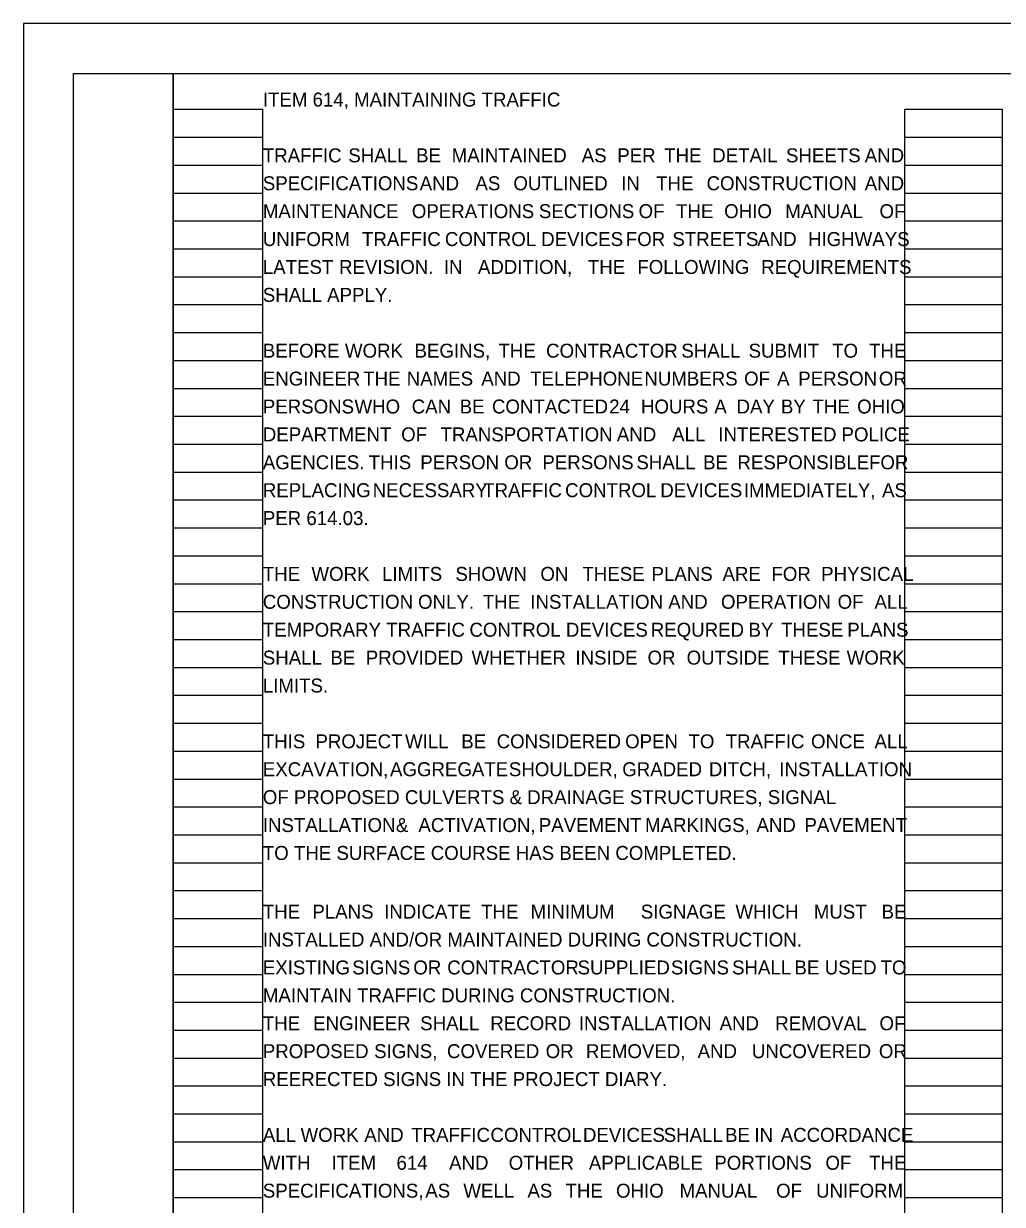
# Model space of a CAD drawing. Extents: x 0 to 34, y 0 to 22.
# Drawn here: x 0 to 9.82, y 10.15 to 22 of the extents above; entities that cross this region are included whole.
import ezdxf

# ---------------------------------------------------------------- set-up
doc = ezdxf.new("R2010")
doc.units = 0
for name, color, linetype in [('SH_Border', 7, 'Continuous'), ('SH_Cut_Line', 7, 'Continuous'), ('SH_Data', 7, 'Continuous'), ('SH_Text', 7, 'Continuous')]:
    doc.layers.add(name, color=color, linetype=linetype)

msp = doc.modelspace()

# ---------------------------------------------------------------- linework, layer by layer
at = {"layer": 'SH_Border'}
for points in [[(0.5, 21.5), (1.5, 21.5), (1.5, 0.5), (0.5, 0.5)], [(1.5, 21.5), (33.5, 21.5), (33.5, 0.5), (1.5, 0.5)]]:
    msp.add_lwpolyline(points, close=True, dxfattribs=at)
at = {"layer": 'SH_Cut_Line'}
msp.add_lwpolyline([(0, 0), (34, 0), (34, 22), (0, 22)], close=True, dxfattribs=at)
at = {"layer": 'SH_Data'}
for p, q in [((1.5, 0.98), (1.5, 21.14)), ((1.5, 21.14), (2.4, 21.14)), ((2.4, 0.98), (2.4, 21.14)), ((8.84, 0.98), (8.84, 21.14)), ((8.84, 21.14), (9.82, 21.14)), ((9.82, 0.98), (9.82, 21.14)), ((1.5, 20.86), (2.4, 20.86)), ((8.84, 20.86), (9.82, 20.86)), ((1.5, 20.58), (2.4, 20.58)), ((8.84, 20.58), (9.82, 20.58)), ((1.5, 20.3), (2.4, 20.3)), ((8.84, 20.3), (9.82, 20.3)), ((1.5, 20.02), (2.4, 20.02)), ((8.84, 20.02), (9.82, 20.02)), ((1.5, 19.74), (2.4, 19.74)), ((8.84, 19.74), (9.82, 19.74)), ((1.5, 19.46), (2.4, 19.46)), ((8.84, 19.46), (9.82, 19.46)), ((1.5, 19.18), (2.4, 19.18)), ((8.84, 19.18), (9.82, 19.18)), ((1.5, 18.9), (2.4, 18.9)), ((8.84, 18.9), (9.82, 18.9)), ((1.5, 18.62), (2.4, 18.62)), ((8.84, 18.62), (9.82, 18.62)), ((1.5, 18.34), (2.4, 18.34)), ((8.84, 18.34), (9.82, 18.34)), ((1.5, 18.06), (2.4, 18.06)), ((8.84, 18.06), (9.82, 18.06)), ((1.5, 17.78), (2.4, 17.78)), ((8.84, 17.78), (9.82, 17.78)), ((1.5, 17.5), (2.4, 17.5)), ((8.84, 17.5), (9.82, 17.5)), ((1.5, 17.22), (2.4, 17.22)), ((8.84, 17.22), (9.82, 17.22)), ((1.5, 16.94), (2.4, 16.94)), ((8.84, 16.94), (9.82, 16.94)), ((1.5, 16.66), (2.4, 16.66)), ((8.84, 16.66), (9.82, 16.66)), ((1.5, 16.38), (2.4, 16.38)), ((8.84, 16.38), (9.82, 16.38)), ((1.5, 16.1), (2.4, 16.1)), ((8.84, 16.1), (9.82, 16.1)), ((1.5, 15.82), (2.4, 15.82)), ((8.84, 15.82), (9.82, 15.82)), ((1.5, 15.54), (2.4, 15.54)), ((8.84, 15.54), (9.82, 15.54)), ((1.5, 15.26), (2.4, 15.26)), ((8.84, 15.26), (9.82, 15.26)), ((1.5, 14.98), (2.4, 14.98)), ((8.84, 14.98), (9.82, 14.98)), ((1.5, 14.7), (2.4, 14.7)), ((8.84, 14.7), (9.82, 14.7)), ((1.5, 14.42), (2.4, 14.42)), ((8.84, 14.42), (9.82, 14.42)), ((1.5, 14.14), (2.4, 14.14)), ((8.84, 14.14), (9.82, 14.14)), ((1.5, 13.86), (2.4, 13.86)), ((8.84, 13.86), (9.82, 13.86)), ((1.5, 13.58), (2.4, 13.58)), ((8.84, 13.58), (9.82, 13.58)), ((1.5, 13.3), (2.4, 13.3)), ((8.84, 13.3), (9.82, 13.3)), ((1.5, 13.02), (2.4, 13.02)), ((8.84, 13.02), (9.82, 13.02)), ((1.5, 12.74), (2.4, 12.74)), ((8.84, 12.74), (9.82, 12.74)), ((1.5, 12.46), (2.4, 12.46)), ((8.84, 12.46), (9.82, 12.46)), ((1.5, 12.18), (2.4, 12.18)), ((8.84, 12.18), (9.82, 12.18)), ((1.5, 11.9), (2.4, 11.9)), ((8.84, 11.9), (9.82, 11.9)), ((1.5, 11.62), (2.4, 11.62)), ((8.84, 11.62), (9.82, 11.62)), ((1.5, 11.34), (2.4, 11.34)), ((8.84, 11.34), (9.82, 11.34)), ((1.5, 11.06), (2.4, 11.06)), ((8.84, 11.06), (9.82, 11.06)), ((1.5, 10.78), (2.4, 10.78)), ((8.84, 10.78), (9.82, 10.78)), ((1.5, 10.5), (2.4, 10.5)), ((8.84, 10.5), (9.82, 10.5)), ((1.5, 10.22), (2.4, 10.22)), ((8.84, 10.22), (9.82, 10.22))]:
    msp.add_line(p, q, dxfattribs=at)

# ---------------------------------------------------------------- texts
at = {"layer": 'SH_Text'}
for s, p in [('ITEM 614, MAINTAINING TRAFFIC', (2.4, 21.168)), ('TRAFFIC ', (2.4, 20.608)), ('SHALL ', (3.258, 20.608)), ('BE ', (3.938, 20.608)), ('MAINTAINED ', (4.295, 20.608)), ('AS ', (5.599, 20.608)), ('PER ', (5.956, 20.608)), ('THE ', (6.427, 20.608)), ('DETAIL ', (6.909, 20.608)), ('SHEETS ', (7.649, 20.608)), ('AND ', (8.439, 20.608)), ('SPECIFICATIONS ', (2.4, 20.328)), ('AND ', (3.974, 20.328)), ('AS ', (4.533, 20.328)), ('OUTLINED ', (4.914, 20.328)), ('IN ', (5.995, 20.328)), ('THE ', (6.346, 20.328)), ('CONSTRUCTION ', (6.852, 20.328)), ('AND ', (8.439, 20.328)), ('MAINTENANCE ', (2.4, 20.048)), ('OPERATIONS ', (3.895, 20.048)), ('SECTIONS ', (5.17, 20.048)), ('OF ', (6.17, 20.048)), ('THE ', (6.546, 20.048)), ('OHIO ', (7.029, 20.048)), ('MANUAL ', (7.641, 20.048)), ('OF ', (8.587, 20.048)), ('UNIFORM ', (2.4, 19.768)), ('TRAFFIC ', (3.395, 19.768)), ('CONTROL ', (4.227, 19.768)), ('DEVICES ', (5.193, 19.768)), ('FOR ', (6.042, 19.768)), ('STREETS ', (6.509, 19.768)), ('AND ', (7.361, 19.768)), ('HIGHWAYS ', (7.87, 19.768)), ('LATEST ', (2.4, 19.488)), ('REVISION. ', (3.165, 19.488)), ('IN ', (4.216, 19.488)), ('ADDITION, ', (4.558, 19.488)), ('THE ', (5.661, 19.488)), ('FOLLOWING ', (6.158, 19.488)), ('REQUIREMENTS ', (7.4, 19.488)), ('SHALL APPLY.', (2.4, 19.208)), ('BEFORE ', (2.4, 18.648)), ('WORK ', (3.224, 18.648)), ('BEGINS, ', (3.922, 18.648)), ('THE ', (4.764, 18.648)), ('CONTRACTOR ', (5.242, 18.648)), ('SHALL ', (6.599, 18.648)), ('SUBMIT ', (7.274, 18.648)), ('TO ', (8.112, 18.648)), ('THE ', (8.483, 18.648)), ('ENGINEER ', (2.4, 18.368)), ('THE ', (3.407, 18.368)), ('NAMES ', (3.844, 18.368)), ('AND ', (4.592, 18.368)), ('TELEPHONE ', (5.082, 18.368)), ('NUMBERS ', (6.228, 18.368)), ('OF ', (7.229, 18.368)), ('A ', (7.56, 18.368)), ('PERSON ', (7.772, 18.368)), ('OR ', (8.581, 18.368)), ('PERSONS ', (2.4, 18.088)), ('WHO ', (3.32, 18.088)), ('CAN ', (3.894, 18.088)), ('BE ', (4.375, 18.088)), ('CONTACTED ', (4.699, 18.088)), ('24 ', (5.875, 18.088)), ('HOURS ', (6.194, 18.088)), ('A ', (6.93, 18.088)), ('DAY ', (7.153, 18.088)), ('BY ', (7.598, 18.088)), ('THE ', (7.915, 18.088)), ('OHIO ', (8.363, 18.088)), ('DEPARTMENT ', (2.4, 17.808)), ('OF ', (3.788, 17.808)), ('TRANSPORTATION ', (4.183, 17.808)), ('AND ', (5.952, 17.808)), ('ALL ', (6.507, 17.808)), ('INTERESTED ', (6.97, 17.808)), ('POLICE ', (8.206, 17.808)), ('AGENCIES. ', (2.4, 17.528)), ('THIS ', (3.462, 17.528)), ('PERSON ', (3.98, 17.528)), ('OR ', (4.823, 17.528)), ('PERSONS ', (5.205, 17.528)), ('SHALL ', (6.148, 17.528)), ('BE ', (6.817, 17.528)), ('RESPONSIBLE ', (7.162, 17.528)), ('FOR ', (8.482, 17.528)), ('REPLACING ', (2.4, 17.248)), ('NECESSARY ', (3.502, 17.248)), ('TRAFFIC ', (4.611, 17.248)), ('CONTROL ', (5.433, 17.248)), ('DEVICES ', (6.388, 17.248)), ('IMMEDIATELY, ', (7.226, 17.248)), ('AS ', (8.613, 17.248)), ('PER 614.03.', (2.4, 16.968)), ('THE ', (2.4, 16.408)), ('WORK ', (2.888, 16.408)), ('LIMITS ', (3.596, 16.408)), ('SHOWN ', (4.332, 16.408)), ('ON ', (5.185, 16.408)), ('THESE ', (5.607, 16.408)), ('PLANS ', (6.3, 16.408)), ('ARE ', (7.012, 16.408)), ('FOR ', (7.503, 16.408)), ('PHYSICAL ', (8.002, 16.408)), ('CONSTRUCTION ', (2.4, 16.128)), ('ONLY. ', (3.957, 16.128)), ('THE ', (4.607, 16.128)), ('INSTALLATION ', (5.084, 16.128)), ('AND ', (6.468, 16.128)), ('OPERATION ', (6.997, 16.128)), ('OF ', (8.167, 16.128)), ('ALL ', (8.537, 16.128)), ('TEMPORARY ', (2.4, 15.848)), ('TRAFFIC ', (3.638, 15.848)), ('CONTROL ', (4.473, 15.848)), ('DEVICES ', (5.441, 15.848)), ('REQURED ', (6.292, 15.848)), ('BY ', (7.273, 15.848)), ('THESE ', (7.6, 15.848)), ('PLANS ', (8.264, 15.848)), ('SHALL ', (2.4, 15.568)), ('BE ', (3.078, 15.568)), ('PROVIDED ', (3.433, 15.568)), ('WHETHER ', (4.494, 15.568)), ('INSIDE ', (5.536, 15.568)), ('OR ', (6.26, 15.568)), ('OUTSIDE ', (6.652, 15.568)), ('THESE ', (7.572, 15.568)), ('WORK ', (8.258, 15.568)), ('LIMITS.', (2.4, 15.288)), ('THIS ', (2.4, 14.728)), ('PROJECT ', (2.928, 14.728)), ('WILL ', (3.827, 14.728)), ('BE ', (4.391, 14.728)), ('CONSIDERED ', (4.746, 14.728)), ('OPEN ', (6.035, 14.728)), ('TO ', (6.671, 14.728)), ('TRAFFIC ', (7.044, 14.728)), ('ONCE ', (7.9, 14.728)), ('ALL ', (8.537, 14.728)), ('EXCAVATION, ', (2.4, 14.448)), ('AGGREGATE ', (3.676, 14.448)), ('SHOULDER, ', (4.869, 14.448)), ('GRADED ', (6.006, 14.448)), ('DITCH, ', (6.876, 14.448)), ('INSTALLATION ', (7.582, 14.448)), ('OF PROPOSED CULVERTS & DRAINAGE STRUCTURES, SIGNAL', (2.4, 14.168)), ('INSTALLATION ', (2.4, 13.888)), ('& ', (3.735, 13.888)), ('ACTIVATION, ', (3.961, 13.888)), ('PAVEMENT ', (5.169, 13.888)), ('MARKINGS, ', (6.235, 13.888)), ('AND ', (7.353, 13.888)), ('PAVEMENT ', (7.834, 13.888)), ('TO THE SURFACE COURSE HAS BEEN COMPLETED.', (2.4, 13.608)), ('THE ', (2.4, 13.019)), ('PLANS ', (2.897, 13.019)), ('INDICATE ', (3.617, 13.019)), ('THE ', (4.59, 13.019)), ('MINIMUM ', (5.087, 13.019)), ('SIGNAGE ', (6.192, 13.019)), ('WHICH ', (7.142, 13.019)), ('MUST ', (7.928, 13.019)), ('BE ', (8.608, 13.019)), ('INSTALLED AND/OR MAINTAINED DURING CONSTRUCTION.', (2.4, 12.739)), ('EXISTING ', (2.4, 12.459)), ('SIGNS ', (3.297, 12.459)), ('OR ', (3.91, 12.459)), ('CONTRACTOR ', (4.25, 12.459)), ('SUPPLIED ', (5.558, 12.459)), ('SIGNS ', (6.495, 12.459)), ('SHALL ', (7.108, 12.459)), ('BE ', (7.734, 12.459)), ('USED ', (8.038, 12.459)), ('TO ', (8.598, 12.459)), ('MAINTAIN TRAFFIC DURING CONSTRUCTION.', (2.4, 12.179)), ('THE ', (2.4, 11.899)), ('ENGINEER ', (2.905, 11.899)), ('SHALL ', (3.979, 11.899)), ('RECORD ', (4.682, 11.899)), ('INSTALLATION ', (5.571, 11.899)), ('AND ', (6.983, 11.899)), ('REMOVAL ', (7.541, 11.899)), ('OF ', (8.587, 11.899)), ('PROPOSED ', (2.4, 11.619)), ('SIGNS, ', (3.517, 11.619)), ('COVERED ', (4.248, 11.619)), ('OR ', (5.238, 11.619)), ('REMOVED, ', (5.642, 11.619)), ('AND ', (6.762, 11.619)), ('UNCOVERED ', (7.307, 11.619)), ('OR ', (8.581, 11.619)), ('REERECTED SIGNS IN THE PROJECT DIARY.', (2.4, 11.339)), ('ALL ', (2.4, 10.779)), ('WORK ', (2.779, 10.779)), ('AND ', (3.418, 10.779)), ('TRAFFIC ', (3.889, 10.779)), ('CONTROL ', (4.684, 10.779)), ('DEVICES ', (5.612, 10.779)), ('SHALL ', (6.422, 10.779)), ('BE ', (7.038, 10.779)), ('IN ', (7.332, 10.779)), ('ACCORDANCE ', (7.596, 10.779)), ('WITH ', (2.4, 10.499)), ('ITEM ', (3.089, 10.499)), ('614 ', (3.741, 10.499)), ('AND ', (4.269, 10.499)), ('OTHER ', (4.867, 10.499)), ('APPLICABLE ', (5.671, 10.499)), ('PORTIONS ', (6.93, 10.499)), ('OF ', (8.045, 10.499)), ('THE ', (8.483, 10.499)), ('SPECIFICATIONS, ', (2.4, 10.219)), ('AS ', (4.03, 10.219)), ('WELL ', (4.412, 10.219)), ('AS ', (5.055, 10.219)), ('THE ', (5.437, 10.219)), ('OHIO ', (5.944, 10.219)), ('MANUAL ', (6.581, 10.219)), ('OF ', (7.55, 10.219)), ('UNIFORM ', (7.951, 10.219))]:
    msp.add_text(s, height=0.14, dxfattribs=at).set_placement(p)

doc.saveas('drawing.dxf')
